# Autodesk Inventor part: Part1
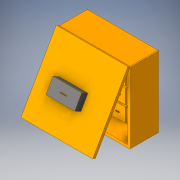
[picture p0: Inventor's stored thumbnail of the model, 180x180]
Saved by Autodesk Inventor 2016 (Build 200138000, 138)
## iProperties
Created: 2019-02
Part Number: Part1
Material: Generic
Document SubType Name: Modeling
Designer: fab
Density: 1 g/cm^3
Appearance: Default
Author: fab
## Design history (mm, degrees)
sketch "Sketch1"
  geometry: L1 (0, 0)-(500, 0); L2 (500, 0)-(500, 500); L3 (500, 500)-(0, 500); L4 (0, 500)-(0, 0); L5 (20, 480)-(480, 480); L6 (480, 480)-(480, 20); L7 (480, 20)-(20, 20); L8 (20, 20)-(20, 480)
  constraints: 16 end point, 4 parallel, 2 perpendicular, 1 horizontal, 3 other
  dimensions: "d0" = 500 distance of L3.end L2.end; "d1" = 500 distance of L2.end L1.end; "d2" = 20 distance between parallel lines of L3 L5
extrude "Extrusion1" new body sketch "Sketch1" distance "d3" = 20; taper "d4" = 0 deg
extrude "Extrusion2" join sketch "Sketch1" distance "d5" = 200; taper "d6" = 0 deg
sketch "Sketch2"
  geometry: L1 (30, 30)-(130, 30); L2 (130, 30)-(130, 130); L3 (130, 130)-(30, 130); L4 (30, 130)-(30, 30); L5 (20, 20)-(20, 480) reference; L6 (480, 20)-(20, 20) reference; L7 (30, 142)-(130, 142); L8 (130, 142)-(130, 242); L9 (130, 242)-(30, 242); L10 (30, 242)-(30, 142); L11 (30, 254)-(130, 254); L12 (130, 254)-(130, 354); L13 (130, 354)-(30, 354); L14 (30, 354)-(30, 254); L15 (30, 366)-(130, 366); L16 (130, 366)-(130, 466); L17 (130, 466)-(30, 466); L18 (30, 466)-(30, 366); L19 (142, 30)-(242, 30); L20 (242, 30)-(242, 130); L21 (242, 130)-(142, 130); L22 (142, 130)-(142, 30); L23 (142, 142)-(242, 142); L24 (242, 142)-(242, 242); L25 (242, 242)-(142, 242); L26 (142, 242)-(142, 142); L27 (142, 254)-(242, 254); L28 (242, 254)-(242, 354); L29 (242, 354)-(142, 354); L30 (142, 354)-(142, 254); L31 (142, 366)-(242, 366); L32 (242, 366)-(242, 466); L33 (242, 466)-(142, 466); L34 (142, 466)-(142, 366); L35 (254, 30)-(354, 30); L36 (354, 30)-(354, 130); L37 (354, 130)-(254, 130); L38 (254, 130)-(254, 30); L39 (254, 142)-(354, 142); L40 (354, 142)-(354, 242); L41 (354, 242)-(254, 242); L42 (254, 242)-(254, 142); L43 (254, 254)-(354, 254); L44 (354, 254)-(354, 354); L45 (354, 354)-(254, 354); L46 (254, 354)-(254, 254); L47 (254, 366)-(354, 366); L48 (354, 366)-(354, 466); L49 (354, 466)-(254, 466); L50 (254, 466)-(254, 366); L51 (366, 30)-(466, 30); L52 (466, 30)-(466, 130); L53 (466, 130)-(366, 130); L54 (366, 130)-(366, 30); L55 (366, 142)-(466, 142); L56 (466, 142)-(466, 242); L57 (466, 242)-(366, 242); L58 (366, 242)-(366, 142); L59 (366, 254)-(466, 254); L60 (466, 254)-(466, 354); L61 (466, 354)-(366, 354); L62 (366, 354)-(366, 254); L63 (366, 366)-(466, 366); L64 (466, 366)-(466, 466)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; 1 further point
  constraints: 128 end point, 2 horizontal, 2 parallel, 1 perpendicular, 1 vertical, 120 other
  dimensions: "d7" = 100 distance of L3.end L2.end; "d8" = 100 distance of L2.end L1.end; "d9" = 10 distance between parallel lines of L4 L5; "d10" = 10 distance between parallel lines of L1 L6; "d13" = 112 distance of L1.start L7.start; "d16" = 112 distance of L1.start L19.start
extrude "Extrusion3" join sketch "Sketch2" distance "d19" = 70; taper "d20" = 0 deg
sketch "Sketch3"
  geometry: L1 (189.251, 122.496)-(289.251, 122.496); L2 (289.251, 122.496)-(289.251, 87.496); L3 (289.251, 87.496)-(189.251, 87.496); L4 (189.251, 87.496)-(189.251, 122.496); C1 r 15 at (110.357, 104.996); C2 r 15 at (363.647, 104.996); 1 further point
  constraints: 8 end point, 2 centre point, 2 parallel, 1 horizontal, 1 perpendicular
  dimensions: "d21" = 100 distance of L1.start L1.end; "d22" = 35 distance between parallel lines of L1 L3; "d23" = 30 diameter of C1; "d24" = 30 diameter of C2
extrude "Extrusion4" join sketch "Sketch3" distance "d25" = 10; taper "d26" = 0 deg
sketch "Sketch4"
  geometry: L1 (44.922, 429.624)-(115.65, 429.624); L2 (115.65, 429.624)-(115.65, 396.172); L3 (115.65, 396.172)-(44.922, 396.172); L4 (44.922, 396.172)-(44.922, 429.624); L5 (268.876, 394.719)-(268.876, 428.172); L6 (268.876, 428.172)-(339.603, 428.172); L7 (339.603, 428.172)-(339.603, 394.719); L8 (339.603, 394.719)-(268.876, 394.719); L9 (42.451, 290.77)-(42.451, 324.222); L10 (42.451, 324.222)-(113.179, 324.222); L11 (113.179, 324.222)-(113.179, 290.77); L12 (113.179, 290.77)-(42.451, 290.77); L13 (158.411, 397.61)-(158.411, 431.062); L14 (158.411, 431.062)-(229.139, 431.062); L15 (229.139, 431.062)-(229.139, 397.61); L16 (229.139, 397.61)-(158.411, 397.61); L17 (381.062, 395.288)-(381.062, 428.741); L18 (381.062, 428.741)-(451.79, 428.741); L19 (451.79, 428.741)-(451.79, 395.288); L20 (451.79, 395.288)-(381.062, 395.288); L21 (156.375, 290.671)-(156.375, 324.124); L22 (156.375, 324.124)-(227.102, 324.124); L23 (227.102, 324.124)-(227.102, 290.671); L24 (227.102, 290.671)-(156.375, 290.671); L25 (270.448, 289.5)-(270.448, 322.953); L26 (270.448, 322.953)-(341.176, 322.953); L27 (341.176, 322.953)-(341.176, 289.5); L28 (341.176, 289.5)-(270.448, 289.5); L29 (384.699, 287.179)-(384.699, 320.631); L30 (384.699, 320.631)-(455.427, 320.631); L31 (455.427, 320.631)-(455.427, 287.179); L32 (455.427, 287.179)-(384.699, 287.179); L33 (44.125, 171.143)-(44.125, 204.596); L34 (44.125, 204.596)-(114.853, 204.596); L35 (114.853, 204.596)-(114.853, 171.143); L36 (114.853, 171.143)-(44.125, 171.143); L37 (157.272, 174.492)-(157.272, 207.945); L38 (157.272, 207.945)-(228, 207.945); L39 (228, 207.945)-(228, 174.492); L40 (228, 174.492)-(157.272, 174.492); L41 (274.53, 171.382)-(274.53, 204.835); L42 (274.53, 204.835)-(345.258, 204.835); L43 (345.258, 204.835)-(345.258, 171.382); L44 (345.258, 171.382)-(274.53, 171.382); L45 (380.631, 176.493)-(380.631, 209.945); L46 (380.631, 209.945)-(451.359, 209.945); L47 (451.359, 209.945)-(451.359, 176.493); L48 (451.359, 176.493)-(380.631, 176.493); L49 (45.191, 62.998)-(45.191, 96.45); L50 (45.191, 96.45)-(115.919, 96.45); L51 (115.919, 96.45)-(115.919, 62.998); L52 (115.919, 62.998)-(45.191, 62.998); L53 (157.164, 60.475)-(157.164, 93.928); L54 (157.164, 93.928)-(227.892, 93.928); L55 (227.892, 93.928)-(227.892, 60.475); L56 (227.892, 60.475)-(157.164, 60.475); L57 (267.375, 60.888)-(267.375, 94.341); L58 (267.375, 94.341)-(338.103, 94.341); L59 (338.103, 94.341)-(338.103, 60.888); L60 (338.103, 60.888)-(267.375, 60.888); L61 (379.935, 57.779)-(379.935, 91.231); L62 (379.935, 91.231)-(450.663, 91.231); L63 (450.663, 91.231)-(450.663, 57.779); L64 (450.663, 57.779)-(379.935, 57.779); 1 further point
  constraints: 32 other
extrude "Extrusion5" join sketch "Sketch4" distance "d27" = 5; taper "d28" = 0 deg
sketch "Sketch5"
  geometry: L1 (208.216, 142.864)-(277.506, 142.864); L2 (277.506, 142.864)-(277.506, 128.866); L3 (277.506, 128.866)-(208.216, 128.866); L4 (208.216, 128.866)-(208.216, 142.864); L5 (346.096, 141.115)-(390.89, 141.115); L6 (390.89, 141.115)-(390.89, 126.067); L7 (390.89, 126.067)-(346.096, 126.067); L8 (346.096, 126.067)-(346.096, 141.115); L9 (88.884, 140.415)-(143.126, 140.415); L10 (143.126, 140.415)-(143.126, 126.767); L11 (143.126, 126.767)-(88.884, 126.767); L12 (88.884, 126.767)-(88.884, 140.415); 1 further point
  constraints: 6 other
fillet "Fillet1" dims "d29" = 5
sketch "Sketch6"
  geometry: L1 (-458.442, 69.561)-(-441.031, 59.72); L2 (-441.031, 59.72)-(-195, 495); L3 (-195, 495)-(-212.411, 504.841); L4 (-212.411, 504.841)-(-458.442, 69.561); L5 (-195, 495)-(-195, 490) reference; L6 (-195, 490)-(0, 490) reference; L7 (0, 490)-(0, 495) reference; L8 (0, 495)-(-195, 495) reference; L9 (-195, 490)-(-195, 495) reference; 1 further point
  constraints: 8 end point, 2 parallel, 1 perpendicular
  dimensions: "d30" = 20 distance of L2.end L3.end; "d31" = 500 distance of L2.end L1.end
extrude "Extrusion6" join sketch "Sketch6" distance "d32" = 500; taper "d33" = 0 deg
fillet "Fillet2" dims "d34" = 5
sketch "Sketch8"
  geometry: L1 (349, 179.408)-(249, 179.408) reference; L2 (125, 363.966)-(125, 276.91) reference; L3 (325, 179.408)-(125, 179.408); L4 (125, 179.408)-(125, 279.408); L5 (125, 279.408)-(325, 279.408); L6 (325, 279.408)-(325, 179.408); 1 further point
  constraints: 8 end point, 2 parallel, 2 point on line, 1 horizontal, 1 perpendicular
  dimensions: "d35" = 200 distance of L3.start L3.end; "d36" = 100 distance between parallel lines of L3 L5
extrude "Extrusion7" join sketch "Sketch8" distance "d37" = 50; taper "d38" = 0 deg
sketch "Sketch9"
  geometry: L1 (163.603, 247.524)-(287.811, 247.524); L2 (287.811, 247.524)-(287.811, 206.433); L3 (287.811, 206.433)-(163.603, 206.433); L4 (163.603, 206.433)-(163.603, 247.524); 1 further point
  constraints: 2 other
emboss "Emboss1" sketch "Sketch9" dims "d39" = 5, "d40" = 0
body "Solid1"
node "Projected Loop1"
